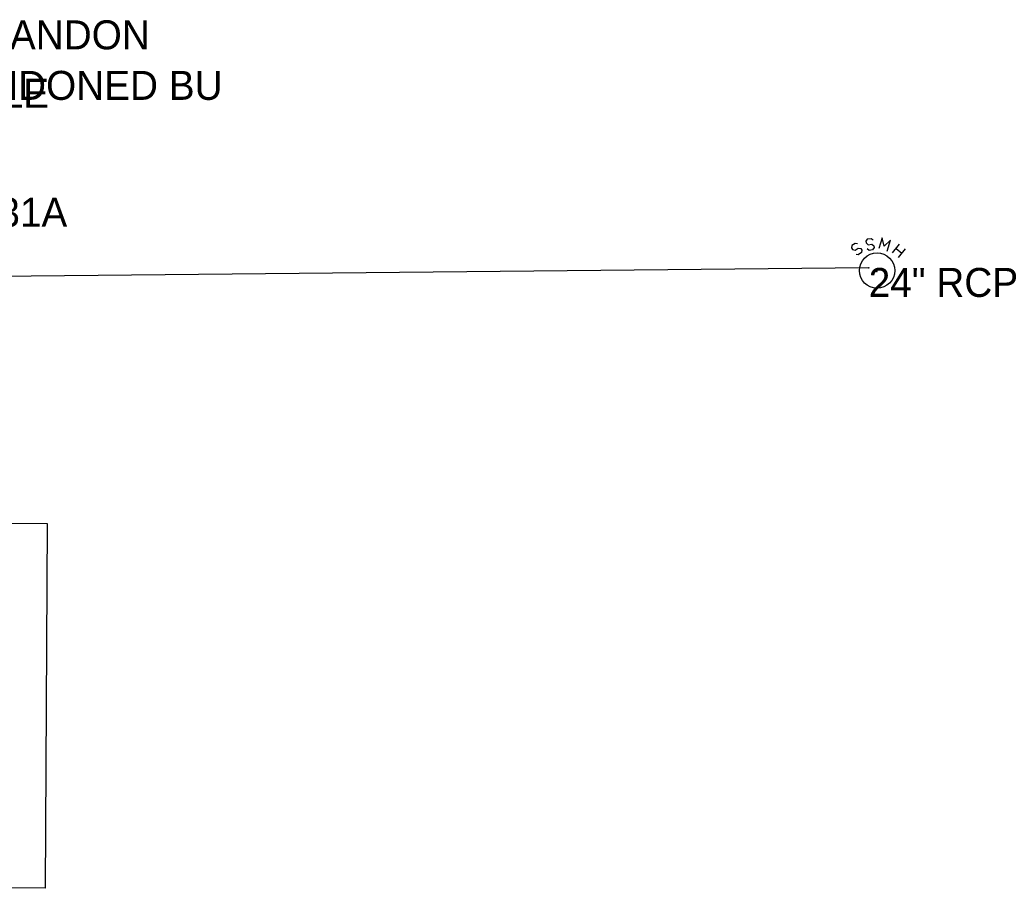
# Model space of a CAD drawing. Extents: x 1304270 to 1306561, y 1876019 to 1876752.
# Drawn here: x 1306389.1 to 1306561, y 1876311.8 to 1876461.6 of the extents above; entities that cross this region are included whole.
import ezdxf

# ---------------------------------------------------------------- set-up
doc = ezdxf.new("R2010")
doc.units = 0
for name, color, linetype in [('S_BUILDING', 7, 'Continuous'), ('S_BUILDING_ANNOT', 7, 'Continuous'), ('S_PRIMARY_CTL_ANNOT', 7, 'Continuous'), ('S_SANITARY_SEWER', 7, 'Continuous'), ('S_SANITARY_SEWER_ANNOT', 7, 'Continuous'), ('S_SURVEY_TEXT_ANNOT', 7, 'Continuous'), ('S_TREE_ANNOT', 7, 'Continuous'), ('S_UTL_PT_SYM', 7, 'Continuous')]:
    doc.layers.add(name, color=color, linetype=linetype)

msp = doc.modelspace()

# ---------------------------------------------------------------- linework, layer by layer
at = {"layer": 'S_BUILDING'}
msp.add_lwpolyline([(1306393.78, 1876374.66), (1306393.43, 1876311.79), (1306357.34, 1876311.99), (1306357.57, 1876354.84), (1306359.66, 1876354.83), (1306359.74, 1876370.2), (1306372.64, 1876370.13), (1306372.67, 1876374.78)], close=True, dxfattribs=at)
at = {"layer": 'S_SANITARY_SEWER'}
for p, q in [((1306533.21, 1876423.01), (1306532.66, 1876422.63)), ((1306533.63, 1876422.94), (1306533.21, 1876423.01)), ((1306539.64, 1876421.39), (1306540.88, 1876422.86)), ((1306532.66, 1876422.63), (1306532.59, 1876422.24)), ((1306532.59, 1876422.24), (1306532.78, 1876421.97)), ((1306532.78, 1876421.97), (1306533.21, 1876421.85)), ((1306533.21, 1876421.85), (1306533.75, 1876422.2)), ((1306533.75, 1876421.04), (1306533.36, 1876421.12)), ((1306533.75, 1876422.2), (1306534.21, 1876422.12)), ((1306534.29, 1876421.43), (1306533.75, 1876421.04)), ((1306534.21, 1876422.12), (1306534.37, 1876421.85)), ((1306534.37, 1876421.85), (1306534.29, 1876421.43)), ((1306540.3, 1876422.16), (1306541.27, 1876421.35)), ((1306541.85, 1876422.05), (1306540.61, 1876420.57)), ((1306535.55, 1876418.78), (1306311.23, 1876416.59))]:
    msp.add_line(p, q, dxfattribs=at)
for points in [[(1306536.31, 1876423.56), (1306535.96, 1876423.83), (1306535.3, 1876423.75), (1306535.07, 1876423.4), (1306535.1, 1876423.09), (1306535.45, 1876422.78), (1306536.07, 1876422.9), (1306536.46, 1876422.59), (1306536.5, 1876422.28), (1306536.23, 1876421.89), (1306535.61, 1876421.81), (1306535.26, 1876422.08)], [(1306538.75, 1876421.7), (1306539.29, 1876423.56), (1306538.24, 1876422.55), (1306537.86, 1876423.98), (1306537.31, 1876422.12)]]:
    msp.add_lwpolyline(points, dxfattribs=at)
msp.add_circle((1306536.99, 1876418.32), 3.05, dxfattribs=at)
at = {"layer": 'S_UTL_PT_SYM'}
for points in [[(1306535.55, 1876418.78), (1306535.55, 1876418.83), (1306535.55, 1876418.78), (1306535.5, 1876418.78), (1306535.55, 1876418.78), (1306535.55, 1876418.73), (1306535.55, 1876418.78), (1306535.6, 1876418.78)], [(1306536.97, 1876418.14), (1306536.97, 1876418.19), (1306536.97, 1876418.14), (1306536.92, 1876418.14), (1306536.97, 1876418.14), (1306536.97, 1876418.09), (1306536.97, 1876418.14), (1306537.02, 1876418.14)]]:
    msp.add_lwpolyline(points, dxfattribs=at)

# ---------------------------------------------------------------- texts
at = {"layer": 'S_BUILDING_ANNOT'}
msp.add_text('1STRY WOOD BRICK ABANDON', height=5, dxfattribs=at).set_placement((1306309.34, 1876456.5))
at = {"layer": 'S_PRIMARY_CTL_ANNOT'}
msp.add_text('PD:AHTD GPS #350031A', height=5, dxfattribs=at).set_placement((1306319.59, 1876425.88))
at = {"layer": 'S_SANITARY_SEWER_ANNOT'}
msp.add_text('24" RCP', height=5, dxfattribs=at).set_placement((1306535.55, 1876413.78))
at = {"layer": 'S_SURVEY_TEXT_ANNOT'}
msp.add_text('1STORY WOOD STUCCO BU ABANDONED BU', height=5, dxfattribs=at).set_placement((1306277.32, 1876447.78))
at = {"layer": 'S_TREE_ANNOT'}
msp.add_text('CRPE MURTLE', height=5, dxfattribs=at).set_placement((1306346.19, 1876446.41))

doc.saveas('drawing.dxf')
